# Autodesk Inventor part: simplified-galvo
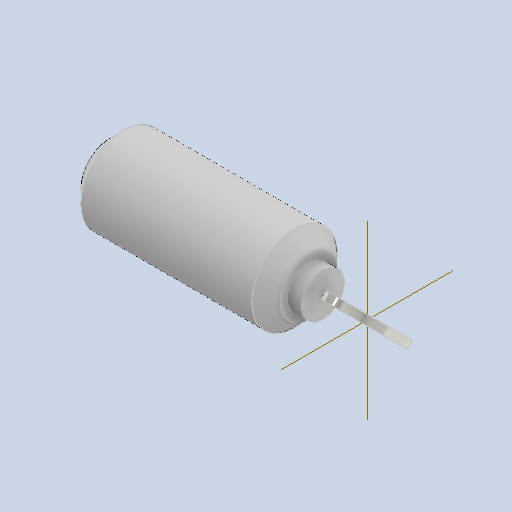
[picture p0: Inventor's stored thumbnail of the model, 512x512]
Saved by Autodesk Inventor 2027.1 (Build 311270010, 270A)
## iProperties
Created: 2026-08
Part Number: simplified-galvo
Material: Generic
Document SubType Name: Modeling
Designer: dunge
Density: 1 g/cm^3
Appearance: Default
Author: dunge
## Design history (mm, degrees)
sketch "Sketch1"
  geometry: L1 (2.54, 7.62)-(38.1, 7.62); L2 (38.1, 7.62)-(38.1, 0); L3 (38.1, 0)-(2.54, 0); L4 (2.54, 0)-(2.54, 7.62); L5 (2.54, 3.81)-(0, 3.81); L6 (0, 3.81)-(0, 0); L7 (0, 0)-(2.54, 0); L8 (2.54, 0)-(2.54, 3.81); 1 further point
  constraints: 16 end point, 4 parallel, 2 horizontal, 2 perpendicular, 1 coincident, 1 midpoint
  dimensions: "d0" = 38.1 distance between parallel lines of L2 L6; "d1" = 7.62 distance of L1.end L2.end; "d2" = 2.54 distance of L6.end L3.end; "d3" = 3.81 distance of L5.end L6.end
revolve "Revolution1" sketch "Sketch1" stored, may be unused: angle "d4" = 90 deg
sketch "Sketch2"
  geometry: L1 (0, 0)-(-3.81, 0); L2 (-3.81, 0)-(-3.81, 0.381); L3 (-3.81, 0.381)-(0, 0.381); L4 (0, 0.381)-(0, 0)
  constraints: 8 end point, 2 parallel, 1 horizontal, 1 perpendicular
  dimensions: "d5" = 3.81 distance of L2.end L3.end; "d6" = 0.381 distance of L1.end L2.end
revolve "Revolution2" sketch "Sketch2" stored, may be unused: angle "d7" = 90 deg
workpoint "Work Point1"
workplane "Work Plane1"
sketch "Sketch3"
  geometry: L1 (3.81, -0.381)-(3.81, 0.381) reference; C1 r 6.35 at (7.874, 0); 1 further point
  constraints: 1 centre point
  dimensions: "d9" = 12.7 diameter of C1; "d10" = 4.064 distance from line of L1 C1.centre
extrude "Extrusion1" join sketch "Sketch3" stored distance "d11" = 1.27; taper "d12" = 0 deg
chamfer "Chamfer1" distance "d13" = 2.54; stored, may be unused: second distance "d14" = 3.175, angle "d15" = 45 deg
node "LIGHT MATE"
node "LIGHT AXIS"
node "SECONDARY LIGHT AXIS"
body "Solid1"
node "Finishes"
node "Finish1" dims "Finish1_Area" = 227.56771
node "Finish2" dims "Finish2_Area" = 30.35653
other parameters: "d8" = -45 deg
